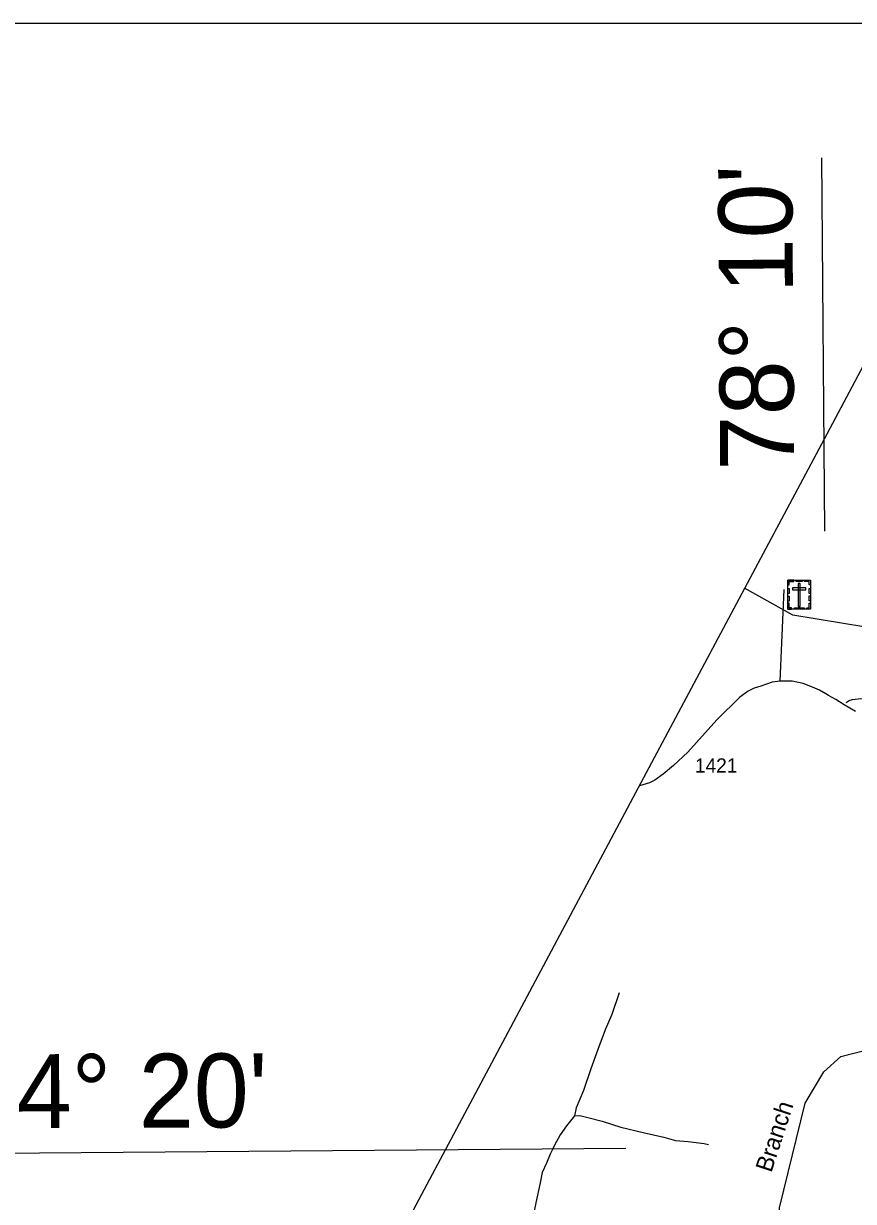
# Model space of a CAD drawing. Extents: x 2225501 to 2309677, y 165449 to 227696.
# Drawn here: x 2244504 to 2251795, y 212881 to 223234 of the extents above; entities that cross this region are included whole.
import ezdxf

# ---------------------------------------------------------------- set-up
doc = ezdxf.new("R2010")
doc.units = 0
for name, color, linetype in [('E_RDY_CMT_EOP', 7, 'Continuous'), ('Old_Level_3', 7, 'Continuous'), ('Old_Level_33', 7, 'Continuous'), ('Old_Level_51', 7, 'Continuous'), ('P_HYD_DRAINAGE_STR_TYPE_LABEL', 7, 'Continuous'), ('P_HYD_Pipe_Pipe_Removal', 7, 'Continuous'), ('P_HYD_PIPE_RCP_CLASS IV_LABEL', 7, 'Continuous'), ('Prop Mkg Solid Yellow Edge Line', 7, 'Continuous'), ('Prop Support', 7, 'Continuous'), ('Scratch_Level_1', 7, 'Continuous'), ('Typical Terminator CELL', 7, 'Continuous')]:
    doc.layers.add(name, color=color, linetype=linetype)

msp = doc.modelspace()

# ---------------------------------------------------------------- linework, layer by layer
at = {"layer": 'Old_Level_3'}
msp.add_line((2251152, 217454), (2251187, 218260), dxfattribs=at)
for points in [[(2251731, 217265), (2251757, 217283), (2251787, 217293), (2251859, 217300), (2252045, 217297), (2252091, 217302), (2252183, 217319), (2252255, 217343), (2252320, 217372), (2252358, 217392), (2252472, 217439)], [(2249737, 214715), (2249671, 214523), (2249615, 214388), (2249550, 214215), (2249489, 214047), (2249424, 213856), (2249359, 213702), (2249345, 213632)], [(2249345, 213632), (2249275, 213544), (2249219, 213465), (2249168, 213376), (2249153, 213344)], [(2249345, 213632), (2249391, 213636), (2249461, 213618), (2249587, 213585), (2249751, 213534), (2249947, 213487), (2250129, 213445), (2250231, 213417), (2250343, 213408), (2250483, 213389), (2250521, 213380)], [(2249153, 213344), (2249130, 213297), (2249098, 213218), (2249060, 213134), (2249042, 213045), (2249004, 212868), (2248962, 212667), (2248920, 212433), (2248883, 212181), (2248860, 212060), (2248849, 212010)]]:
    msp.add_lwpolyline(points, dxfattribs=at)
at = {"layer": 'Old_Level_33'}
msp.add_lwpolyline([(2251814, 217186), (2251712, 217245), (2251639, 217291), (2251576, 217329), (2251551, 217343), (2251496, 217374), (2251435, 217401), (2251354, 217432), (2251255, 217454), (2251152, 217454), (2251082, 217444), (2250980, 217411), (2250923, 217393), (2250871, 217365), (2250797, 217314), (2250596, 217114), (2250340, 216830), (2250215, 216713), (2250122, 216637), (2250051, 216582), (2250002, 216560), (2249914, 216534)], dxfattribs=at)
at = {"layer": 'Old_Level_51'}
msp.add_lwpolyline([(2252865, 222076), (2251537, 219581), (2249903, 216515), (2248210, 213337), (2246231, 209621), (2243743, 204951), (2241922, 201533), (2239717, 197394), (2237003, 192299), (2234601, 187789), (2232019, 182943), (2229513, 178250), (2226734, 173036), (2226255, 172151), (2225501, 170758)], dxfattribs=at)
at = {"layer": 'P_HYD_Pipe_Pipe_Removal'}
msp.add_lwpolyline([(2243856, 191238), (2266254, 191238), (2266254, 223234), (2243856, 223234)], close=True, dxfattribs=at)
at = {"layer": 'P_HYD_PIPE_RCP_CLASS IV_LABEL'}
for p, q in [((2251543, 218772), (2251516, 222054)), ((2243413, 213298), (2249796, 213349))]:
    msp.add_line(p, q, dxfattribs=at)
at = {"layer": 'Prop Mkg Solid Yellow Edge Line'}
for points in [[(2251218, 218342), (2251417, 218342), (2251417, 218087), (2251218, 218087)], [(2251218, 218299), (2251230, 218299), (2251230, 218331), (2251270, 218331), (2251270, 218342), (2251218, 218342)], [(2251218, 218224), (2251218, 218268), (2251230, 218268), (2251230, 218224)], [(2251259, 218274), (2251259, 218255), (2251377, 218255), (2251377, 218274)], [(2251292, 218342), (2251344, 218342), (2251344, 218330), (2251292, 218330)], [(2251327, 218313), (2251309, 218313), (2251309, 218110), (2251327, 218110)], [(2251417, 218299), (2251406, 218299), (2251406, 218331), (2251366, 218331), (2251366, 218342), (2251417, 218342)], [(2251406, 218225), (2251406, 218269), (2251417, 218269), (2251417, 218225)], [(2251218, 218157), (2251218, 218201), (2251230, 218201), (2251230, 218157)], [(2251251, 218087), (2251251, 218099), (2251229, 218099), (2251229, 218139), (2251218, 218139), (2251218, 218087)], [(2251384, 218087), (2251384, 218099), (2251406, 218099), (2251406, 218139), (2251417, 218139), (2251417, 218087)], [(2251406, 218160), (2251406, 218203), (2251417, 218203), (2251417, 218160)], [(2251276, 218099), (2251361, 218099), (2251361, 218087), (2251276, 218087)]]:
    msp.add_lwpolyline(points, close=True, dxfattribs=at)
at = {"layer": 'Prop Support'}
msp.add_lwpolyline([(2251903, 217929), (2251261, 218033), (2250838, 218270)], dxfattribs=at)
at = {"layer": 'Typical Terminator CELL'}
msp.add_lwpolyline([(2250466, 211495), (2250638, 211528), (2250870, 211707), (2251019, 211875), (2251092, 212067), (2251145, 212824), (2251370, 213744), (2251535, 214020), (2251683, 214155), (2252074, 214255), (2252348, 214384), (2252728, 214738)], dxfattribs=at)

# ---------------------------------------------------------------- texts
at = {"layer": 'E_RDY_CMT_EOP'}
msp.add_text('1421', height=125, dxfattribs=at).set_placement((2250403, 216650))
at = {"layer": 'P_HYD_DRAINAGE_STR_TYPE_LABEL'}
for s, rotation, p in [("78° 10'", 90.387, (2251274, 219308)), ("34° 20'", 0.2163, (2243961, 213522))]:
    msp.add_text(s, height=650, rotation=rotation, dxfattribs=at).set_placement(p)
at = {"layer": 'Scratch_Level_1'}
msp.add_text('Branch', height=150, rotation=71.9307, dxfattribs=at).set_placement((2251073, 213128))

doc.saveas('drawing.dxf')
